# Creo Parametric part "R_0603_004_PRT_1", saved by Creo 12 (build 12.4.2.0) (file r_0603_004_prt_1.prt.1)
Units: Custom; MM, KILOGRAM, SECS

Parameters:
  PTC_WM_ITERATION = "0"
  PTC_WM_VERSION = "-.0"
  PTC_WM_LIFECYCLE_STATE = "In Work"
  PTC_WM_LIFECYCLE = "MO_CADDocument"
  PTC_WM_CREATED_BY = "Maximilian Roepper (Z0017RMS: MO)"
  PTC_WM_CREATED_ON = "18-Sep-26 11:36:42 AM"
  PTC_WM_MODIFIED_BY = "Maximilian Roepper (Z0017RMS: MO)"
  PTC_WM_MODIFIED_ON = "18-Sep-26 11:36:46 AM"
  PDMLINKNUMBER = "PDM000071454911"
  PTC_WM_NAME = "r_0603_004_prt_1.prt"
  PTC_WM_NUMBER = "PDM000071454911"

Other parameters: WEIGHT, WEIGHT_FACTOR, WEIGHT_ADD, _MASS_TEMP, _DIFF_TEMP, MC_ERRORS, SUPPLIER

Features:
  1. coordinate system
  2. datum plane "PRT_YZ"
  3. datum plane "PRT_XY"
  4. datum plane "PRT_XZ"
  5. coordinate system
  6. datum axis
  7. datum axis
  8. datum axis
  9. coordinate system
  10. imported feature
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
Other named items: PRT, SIEMENS_MO, DRW_VIEW_ORG, PRT_X, PRT_Y, PRT_Z, CS0, ROUGH_GROB

Layers: 00_STD_CSYS-KSYS, 01_STD_PLANES-EBENEN, 02_STD_AXES-ACHSEN, 03_STD_CSYS-KSYS, 24_IMPORT_FEAT-IMPORT_KE

Surfaces: 18 plane, 8 cylinder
